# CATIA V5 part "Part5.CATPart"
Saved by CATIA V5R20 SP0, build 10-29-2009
Part number: Part5
Bounding box of the stored display mesh (mm): x -6 to 6, y -165 to 175, z -6 to 6
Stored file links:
  E:\Ehsan\Catia\Tamrin\DMU\2\Part5.CATPart
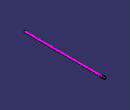
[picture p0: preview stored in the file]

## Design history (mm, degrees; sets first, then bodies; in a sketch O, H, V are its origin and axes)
Body1 (main body)
  Sketch1 on zx-plane, origin (0, 0, 0), H (-1, 0, 0), V (0, 0, 1)
    circle A1 centre (0, 0) radius 4
    radius A1 = 4
  Pad1: profile Sketch1, direction (0, 1, 0), length 165, mirrored extent
  Sketch2 on end face of Pad1, origin (0, 165, 0), H (-1, 0, 0), V (0, 0, 1)
    circle A1 centre (0, 0) radius 6
    projected circle E1 centre (0, 0) radius 4 from edge [face of Pad1 from Sketch1.A1 | end face of Pad1]
    radius A1 = 6
  Pad2: profile Sketch2, direction (0, -1, 0), length 6
  Sketch3 on face of Pad2, origin (0, 165, 0), H (-1, 0, 0), V (0, 0, 1)
    point P1 (3.8971, -2.25)
    point P2 (3.8971, 2.25)
    point P3 (0, 4.5)
    point P4 (-3.8971, 2.25)
    point P5 (-3.8971, -2.25)
    point P6 (0, -4.5)
    point P7 (3.8971, 0)
    line L1 (3.8971, -2.25) -> (3.8971, 2.25)
    line L2 (3.8971, 2.25) -> (0, 4.5)
    line L3 (0, 4.5) -> (-3.8971, 2.25)
    line L4 (-3.8971, 2.25) -> (-3.8971, -2.25)
    line L5 (-3.8971, -2.25) -> (0, -4.5)
    line L6 (0, -4.5) -> (3.8971, -2.25)
    construction line L7 (0, 0) -> (3.8971, 0)
    construction circle A1 centre (0, 0) radius 4.5
    construction arc A2 centre (-3.8971, -2.25) radius 4.5 from (-3.8971, 2.25) to (0, -4.5) cw
    construction arc A3 centre (3.8971, 2.25) radius 4.5 from (0, 4.5) to (3.8971, -2.25) ccw
    horizontal: L7 H
    coincidence: A1 P1, A1 P2, A1 P3, A1 P4, A1 P5, A1 P6, A2 O, A3 O
    midpoint: P7 L1
  Pad3: profile Sketch3, direction (0, 1, 0), length 10
  Chamfer1: length 1, angle 45, on end face of Pad3; start face of Pad1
